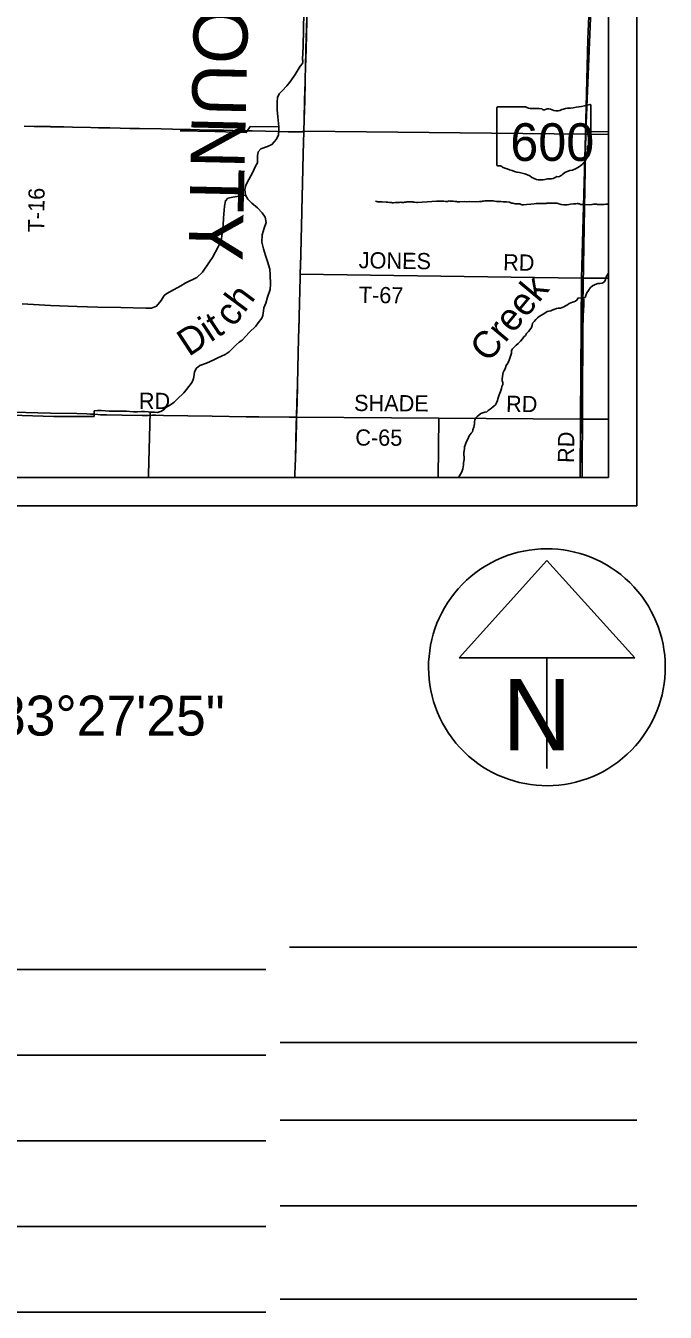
# Model space of a CAD drawing. Extents: x -8.3 to 42.1, y 0 to 22.
# Drawn here: x 6.858 to 9.099, y 11.177 to 15.682 of the extents above; entities that cross this region are included whole.
import ezdxf

# ---------------------------------------------------------------- set-up
doc = ezdxf.new("R2010")
doc.units = 0
for name, color, linetype in [('Default', 7, 'Continuous'), ('GM_X_County_Road', 7, 'Continuous'), ('GM_X_County_Road_Text', 7, 'Continuous'), ('GM_X_County_Text', 7, 'Continuous'), ('GM_X_Minor_River', 7, 'Continuous'), ('GM_X_Minor_River_Text', 7, 'Continuous'), ('GM_X_State_Location', 7, 'Continuous'), ('GM_X_State_Route', 7, 'Continuous'), ('GM_X_State_Shield', 7, 'Continuous'), ('GM_X_Township_Road', 7, 'Continuous'), ('GM_X_Township_Road_Text', 7, 'Continuous'), ('GM_X_US_Route', 7, 'Continuous'), ('SH_Cut_Line', 7, 'Continuous'), ('SH_Data', 7, 'Continuous'), ('SH_Text', 7, 'Continuous')]:
    doc.layers.add(name, color=color, linetype=linetype)

msp = doc.modelspace()

# ---------------------------------------------------------------- linework, layer by layer
at = {"layer": 'Default'}
for points in [[(8.9, 15.3104), (8.9, 16.3044), (8.8613, 16.3047), (8.821, 15.3114)], [(8.9, 14.3033), (8.9, 15.3104), (8.821, 15.3114), (8.8035, 14.3039)], [(8.8012, 14.1), (8.9, 14.1), (8.9, 14.3033), (8.8035, 14.3039)]]:
    msp.add_lwpolyline(points, close=True, dxfattribs=at)
at = {"layer": 'GM_X_County_Road'}
msp.add_lwpolyline([(7.8073, 14.3105), (8.306, 14.307), (8.8027, 14.3043), (8.9, 14.3037)], dxfattribs=at)
at = {"layer": 'GM_X_Minor_River'}
for p, q in [((8.8101, 14.6407), (8.8101, 14.6411)), ((8.8103, 14.6206), (8.8085, 14.1))]:
    msp.add_line(p, q, dxfattribs=at)
for points in [[(7.833, 15.7279), (7.8304, 15.6084), (7.8285, 15.5633), (7.8292, 15.5602), (7.8291, 15.5549), (7.8278, 15.5496), (7.82, 15.5396), (7.8019, 15.5104), (7.7877, 15.4888), (7.7729, 15.4713), (7.7565, 15.4542), (7.7468, 15.4427), (7.7408, 15.4303), (7.7389, 15.4137), (7.7397, 15.3871), (7.7414, 15.3627), (7.7451, 15.3274), (7.7448, 15.3148), (7.7436, 15.2993), (7.7372, 15.2843), (7.7208, 15.2657), (7.7055, 15.2592), (7.6826, 15.2511), (7.6728, 15.2395), (7.6699, 15.2267), (7.67, 15.202), (7.6629, 15.1901), (7.654, 15.1683), (7.6401, 15.1436), (7.6294, 15.1237), (7.626, 15.1078), (7.6278, 15.0884), (7.6365, 15.0746), (7.651, 15.0602), (7.6699, 15.0445), (7.6872, 15.0263), (7.6975, 15.0116), (7.7008, 14.9925), (7.6942, 14.9726), (7.6872, 14.9496), (7.6858, 14.9238), (7.6909, 14.8998), (7.6983, 14.8776), (7.7054, 14.8566), (7.7134, 14.8287), (7.7152, 14.81), (7.7159, 14.777), (7.7143, 14.7581), (7.7049, 14.7317), (7.6991, 14.7102), (7.693, 14.6941), (7.6916, 14.6838), (7.6889, 14.6672), (7.686, 14.6578), (7.6731, 14.6413)], [(7.7451, 15.3274), (7.6448, 15.329), (7.631, 15.3073), (7.5224, 15.3111), (7.399, 15.3134)], [(7.6278, 15.0884), (7.5841, 15.0815), (7.5666, 15.0774), (7.5584, 15.0689), (7.5549, 15.0492), (7.5508, 15.0083), (7.5498, 14.9829), (7.5465, 14.9538), (7.5432, 14.9288), (7.5328, 14.9071), (7.5129, 14.8696), (7.5027, 14.8547), (7.478, 14.8181), (7.4578, 14.8003), (7.4168, 14.7805), (7.4018, 14.7709), (7.3523, 14.7441), (7.3438, 14.7367), (7.3331, 14.7195), (7.3167, 14.6994), (7.2995, 14.6926), (7.2791, 14.6927), (7.1916, 14.6952), (7.1106, 14.696), (7.038, 14.6989), (6.9453, 14.7016), (6.8458, 14.7082)], [(8.3763, 15.0655), (8.3736, 15.0655), (8.371, 15.0652), (8.3679, 15.0656), (8.3615, 15.0661), (8.3555, 15.0669), (8.3452, 15.0674), (8.3415, 15.0679), (8.3361, 15.0664), (8.3335, 15.0661), (8.3293, 15.0665), (8.3229, 15.067), (8.3149, 15.0667), (8.3097, 15.0675), (8.3066, 15.0675), (8.2975, 15.0673), (8.2809, 15.0664), (8.2312, 15.0628), (8.2274, 15.0625), (8.2202, 15.0634), (8.2172, 15.0634), (8.2142, 15.0646), (8.2097, 15.065), (8.2063, 15.0654), (8.1975, 15.0655), (8.1938, 15.0652), (8.1907, 15.0641), (8.1854, 15.0634), (8.182, 15.0631), (8.179, 15.0628), (8.1759, 15.0628), (8.1729, 15.0632), (8.168, 15.0629), (8.1589, 15.063), (8.1551, 15.0627), (8.1524, 15.0627), (8.1475, 15.062), (8.1437, 15.0617), (8.1403, 15.0621), (8.1354, 15.0629), (8.1328, 15.063), (8.1275, 15.0638), (8.1207, 15.0639), (8.1067, 15.0644), (8.1032, 15.0645), (8.0976, 15.0649), (8.0942, 15.065), (8.0915, 15.0654), (8.0881, 15.0662), (8.0844, 15.0674)], [(8.9, 15.0564), (8.8911, 15.0566), (8.8846, 15.0559), (8.8774, 15.056), (8.8748, 15.0556), (8.8695, 15.0553), (8.8668, 15.0553), (8.8619, 15.0558), (8.8585, 15.0562), (8.8544, 15.0566), (8.8513, 15.0567), (8.8479, 15.0564), (8.8422, 15.0553), (8.8346, 15.0546), (8.8191, 15.0552), (8.8119, 15.0553), (8.8055, 15.0558), (8.8025, 15.0558), (8.7991, 15.0574), (8.7964, 15.0582), (8.793, 15.0586), (8.7904, 15.0586), (8.7862, 15.0583), (8.7779, 15.058), (8.7673, 15.0566), (8.7555, 15.0549), (8.7438, 15.0547), (8.7343, 15.0559), (8.7264, 15.0579), (8.7204, 15.0599), (8.717, 15.0603), (8.7143, 15.0607), (8.7109, 15.0604), (8.7052, 15.0597), (8.6984, 15.0598), (8.6874, 15.0603), (8.6844, 15.0604), (8.6817, 15.0596), (8.6764, 15.059), (8.6681, 15.0587), (8.6598, 15.0588), (8.6514, 15.0593), (8.6465, 15.059), (8.6397, 15.0579), (8.6279, 15.0569), (8.6128, 15.0556), (8.6025, 15.055), (8.5984, 15.055), (8.5882, 15.0574), (8.5825, 15.0575), (8.578, 15.058), (8.5738, 15.0584), (8.5651, 15.06), (8.5614, 15.0608), (8.558, 15.062), (8.5531, 15.0636), (8.5425, 15.0649), (8.5315, 15.0654), (8.5236, 15.0659), (8.5152, 15.066), (8.5073, 15.0665), (8.496, 15.0681), (8.4888, 15.0682), (8.4812, 15.0687), (8.4759, 15.0688), (8.4702, 15.0685), (8.4676, 15.0685), (8.463, 15.0674), (8.4592, 15.0667), (8.4565, 15.0664), (8.4512, 15.066), (8.4486, 15.0657), (8.4331, 15.0655), (8.4122, 15.0658), (8.4039, 15.0651), (8.3944, 15.0656), (8.3789, 15.0651), (8.3763, 15.0655)], [(8.9, 14.8154), (8.898, 14.8111), (8.8927, 14.802), (8.8897, 14.7932), (8.8859, 14.7852), (8.8784, 14.7799), (8.8708, 14.7791), (8.8628, 14.7787), (8.8537, 14.7756), (8.8446, 14.771), (8.8359, 14.7633), (8.8299, 14.7549), (8.8239, 14.7462), (8.8209, 14.7367), (8.8184, 14.7305)], [(8.8184, 14.7305), (8.7924, 14.7275), (8.7905, 14.7218), (8.7848, 14.7169), (8.7794, 14.7153), (8.7737, 14.7134), (8.768, 14.7112), (8.762, 14.7085), (8.7563, 14.7039), (8.7502, 14.7009), (8.7437, 14.6967), (8.738, 14.6944), (8.7316, 14.6929), (8.7243, 14.6925), (8.7179, 14.6914), (8.7118, 14.6895), (8.7057, 14.6872), (8.6977, 14.6838), (8.692, 14.6823), (8.686, 14.6804), (8.6806, 14.6773), (8.6719, 14.672), (8.6635, 14.6675), (8.6578, 14.6637), (8.6514, 14.6591), (8.646, 14.6526), (8.6396, 14.6462), (8.6343, 14.6405), (8.6331, 14.6314), (8.6308, 14.6249), (8.6244, 14.6169), (8.6202, 14.6112), (8.6133, 14.6036), (8.6092, 14.5971), (8.6035, 14.5922), (8.5989, 14.5854), (8.5917, 14.577), (8.5841, 14.5686), (8.5772, 14.5626), (8.5685, 14.555), (8.5628, 14.5496), (8.5609, 14.5436), (8.5605, 14.5352), (8.5578, 14.5284), (8.5552, 14.5208), (8.5521, 14.5109), (8.5472, 14.5002), (8.5422, 14.4915), (8.5384, 14.4801), (8.5343, 14.4744), (8.5316, 14.4679), (8.5297, 14.4615), (8.5289, 14.4539), (8.5282, 14.4447), (8.5282, 14.4383), (8.5301, 14.4322), (8.5297, 14.425), (8.527, 14.4185), (8.5255, 14.4109), (8.5221, 14.4003), (8.5198, 14.3946), (8.5167, 14.3892), (8.5152, 14.382), (8.5129, 14.3752), (8.5118, 14.3695), (8.508, 14.3611), (8.5038, 14.3543), (8.4985, 14.3489), (8.492, 14.3436), (8.4856, 14.3391), (8.4791, 14.3341), (8.4738, 14.3299), (8.4673, 14.3284), (8.4601, 14.3265), (8.4533, 14.3235), (8.446, 14.3174), (8.4403, 14.3136), (8.4358, 14.3083), (8.4316, 14.3011), (8.4304, 14.2946), (8.4304, 14.2878), (8.4289, 14.2756), (8.4251, 14.2661), (8.424, 14.26), (8.419, 14.2547), (8.4122, 14.2456), (8.4072, 14.2334), (8.4012, 14.2235), (8.3981, 14.2125), (8.3958, 14.2072), (8.3958, 14.2015), (8.3943, 14.1927), (8.3932, 14.187), (8.3935, 14.1817), (8.3943, 14.1688), (8.3947, 14.1631), (8.3935, 14.1574), (8.3924, 14.1513), (8.392, 14.1437), (8.3897, 14.1304), (8.3878, 14.1236)], [(8.8103, 14.6201), (8.8113, 14.6619), (8.8118, 14.6653), (8.8119, 14.6755), (8.8123, 14.6789), (8.8124, 14.6854), (8.8129, 14.6884), (8.8129, 14.6918), (8.8134, 14.6964), (8.8138, 14.6998), (8.8138, 14.7032), (8.8143, 14.7066), (8.8144, 14.7142), (8.814, 14.7168), (8.8134, 14.7214), (8.8112, 14.7297)], [(7.6731, 14.6413), (7.6651, 14.6294), (7.6417, 14.6073), (7.6292, 14.5944), (7.617, 14.5807), (7.6065, 14.573), (7.596, 14.5642), (7.5839, 14.5524), (7.5714, 14.5402), (7.557, 14.5307), (7.5443, 14.5247), (7.5312, 14.5182), (7.5173, 14.5114), (7.505, 14.5057), (7.4919, 14.5), (7.4689, 14.4915), (7.4561, 14.4828), (7.45, 14.4697), (7.4486, 14.4591), (7.4463, 14.4462), (7.441, 14.4338), (7.4299, 14.4182), (7.422, 14.4074), (7.4118, 14.3959), (7.3884, 14.3738), (7.3786, 14.3638), (7.3654, 14.354), (7.3553, 14.3486), (7.344, 14.3386), (7.3316, 14.331), (7.319, 14.3276), (7.3095, 14.3279), (7.2974, 14.3286), (7.2871, 14.3293), (7.2743, 14.3308), (7.264, 14.3307), (7.2495, 14.3296), (7.2359, 14.3296), (7.2233, 14.3304), (7.2116, 14.3315), (7.1979, 14.3323), (7.1842, 14.3319), (7.1728, 14.3319), (7.1633, 14.3318), (7.1508, 14.3317), (7.1375, 14.3329), (7.1243, 14.3337), (7.1102, 14.3348), (7.0976, 14.3332)], [(8.8128, 14.6311), (8.8127, 14.6311)], [(7.0976, 14.3332), (7.0975, 14.3135), (6.9572, 14.3135), (6.808, 14.3174), (6.8025, 14.1535), (6.8011, 14.1)], [(7.2947, 14.3288), (7.2888, 14.1104), (7.2885, 14.1)], [(8.3878, 14.1236), (8.3855, 14.1175), (8.3817, 14.111), (8.3779, 14.1057), (8.3749, 14.1)]]:
    msp.add_lwpolyline(points, dxfattribs=at)
at = {"layer": 'GM_X_State_Route'}
msp.add_lwpolyline([(7.8327, 15.3119), (8.8198, 15.3016), (8.9, 15.3008)], dxfattribs=at)
at = {"layer": 'GM_X_State_Shield'}
for p, q in [((8.5093, 15.3943), (8.5093, 15.1942)), ((8.609, 15.3978), (8.5125, 15.3978)), ((8.8389, 15.2981), (8.8389, 15.4027)), ((8.8388, 15.2981), (8.8389, 15.2981))]:
    msp.add_line(p, q, dxfattribs=at)
for centre, major_axis, start_param, end_param in [((8.5131, 15.3948), (0.00382, 0), 1.712693, 3.28349), ((8.632, 15.421), (0.037, 0), 4.042523, 4.731795), ((8.6443, 15.2854), (0.133, 0), 1.404758, 1.657858), ((8.6745, 15.3958), (0.0107, 0), 3.836095, 5.185415), ((8.6902, 15.3727), (0.0222, 0), 0.950623, 2.079405), ((8.7188, 15.4044), (0.0267, 0), 4.081561, 5.145723), ((8.766, 15.3367), (0.0703, 0), 1.699011, 2.107814), ((8.7215, 15.6706), (0.3495, 0), 4.814394, 5.042369), ((8.8352, 15.4032), (0.00367, 0), 6.141152, 7.989035), ((8.838, 15.2904), (0.00568, 0), 1.883978, 3.671073), ((8.8019, 15.2771), (0.0341, 0), 5.934695, 6.695948), ((8.8349, 15.2976), (0.00393, 0), 5.05454, 6.418171), ((8.741, 15.2409), (0.0874, 0), 5.101752, 6.440018), ((8.852, 15.2542), (0.0248, 0), 2.387724, 3.262537), ((8.5131, 15.1938), (0.00385, 0), 3.00124, 4.508301), ((8.5137, 15.2143), (0.0294, 0), 4.665946, 4.897461), ((8.5197, 15.1827), (0.0106, 0), 0.519207, 1.627899), ((8.6535, 15.3625), (0.2524, 0), 4.195997, 4.488961), ((8.5783, 15.1043), (0.079, 0), 0.823519, 1.323587), ((8.6637, 15.1817), (0.0501, 0), 4.026481, 4.996735), ((8.6926, 15.1125), (0.0412, 0), 1.495662, 1.94098), ((8.6963, 15.1667), (0.0267, 0), 4.691044, 5.507374), ((8.7204, 15.1473), (0.00752, 0), 1.147584, 2.315152), ((8.7172, 15.1748), (0.0282, 0), 4.937069, 5.64225), ((8.7779, 15.138), (0.0479, 0), 1.647645, 2.488434)]:
    msp.add_ellipse(centre, major_axis=major_axis, ratio=0.8, start_param=start_param, end_param=end_param, dxfattribs=at)
at = {"layer": 'GM_X_Township_Road'}
for p, q in [((7.8204, 14.812), (8.8057, 14.7977)), ((8.8057, 14.7977), (8.9, 14.7971)), ((8.3033, 14.1), (8.306, 14.307)), ((8.8006, 14.1), (8.8027, 14.3043))]:
    msp.add_line(p, q, dxfattribs=at)
for points in [[(7.844, 15.7482), (7.8403, 15.6006), (7.8387, 15.5353), (7.8376, 15.4981), (7.8374, 15.4841), (7.8356, 15.4204), (7.8337, 15.3535), (7.8325, 15.3124), (7.8306, 15.2323), (7.8281, 15.1298), (7.8258, 15.035), (7.8243, 14.9759), (7.8232, 14.9386), (7.8218, 14.8765), (7.8202, 14.8125), (7.8201, 14.8066), (7.8185, 14.7491), (7.8175, 14.7164), (7.8163, 14.6574), (7.8143, 14.5859), (7.8115, 14.4834), (7.8101, 14.4243), (7.8086, 14.3606), (7.8071, 14.311), (7.8064, 14.2876), (7.8034, 14.1648), (7.8025, 14.1415), (7.8014, 14.1104), (7.8015, 14.1089), (7.8013, 14.1027), (7.8013, 14.1), (8.9, 14.1), (8.9, 16.8007)], [(8.8198, 15.3016), (8.828, 15.6349), (8.835, 15.7975), (8.8508, 16.125), (8.8664, 16.6469), (8.8745, 16.8004)], [(2.1, 14.1), (7.8013, 14.1), (7.8013, 14.1027), (7.8015, 14.1089), (7.8014, 14.1104), (7.8025, 14.1415), (7.8034, 14.1648), (7.8064, 14.2876), (7.8071, 14.311), (7.8086, 14.3606), (7.8101, 14.4243), (7.8115, 14.4834), (7.8143, 14.5859), (7.8163, 14.6574), (7.8175, 14.7164), (7.8185, 14.7491), (7.8201, 14.8066), (7.8202, 14.8125), (7.8218, 14.8765), (7.8232, 14.9386), (7.8243, 14.9759), (7.8258, 15.035), (7.8281, 15.1298), (7.8306, 15.2323), (7.8325, 15.3124), (7.8337, 15.3535), (7.8356, 15.4204), (7.8374, 15.4841), (7.8376, 15.4981), (7.8387, 15.5353), (7.8403, 15.6006), (7.844, 15.7482)], [(6.8533, 15.3297), (6.8874, 15.3292), (6.9201, 15.3286), (6.9434, 15.3282), (6.9465, 15.3281), (6.9915, 15.3272), (7.0226, 15.3266), (7.0863, 15.3253), (7.1127, 15.3246), (7.1329, 15.324), (7.1531, 15.3235), (7.1888, 15.3226), (7.2229, 15.322), (7.2571, 15.3215), (7.3333, 15.3201), (7.3721, 15.3192), (7.4001, 15.3188), (7.4358, 15.3179), (7.4668, 15.3172), (7.5135, 15.3163), (7.5383, 15.3159), (7.5507, 15.3157), (7.5834, 15.3149), (7.6222, 15.314), (7.6517, 15.3132), (7.6983, 15.3121), (7.7403, 15.3112), (7.7775, 15.3106), (7.8055, 15.3103), (7.821, 15.31), (7.8242, 15.3101), (7.8273, 15.3104), (7.8297, 15.311), (7.8327, 15.3119)], [(8.8027, 14.3043), (8.8057, 14.7977), (8.8198, 15.3016)], [(6.8271, 14.3279), (6.8582, 14.3272), (6.9001, 14.3262), (6.9452, 14.3253), (7.0368, 14.3234), (7.0726, 14.3226), (7.0849, 14.322), (7.0958, 14.3211), (7.1113, 14.3198), (7.1206, 14.3193), (7.1408, 14.3189), (7.1967, 14.318), (7.2667, 14.3169), (7.2869, 14.3169), (7.3024, 14.3174), (7.3133, 14.3174), (7.3412, 14.317), (7.4267, 14.3157), (7.5121, 14.3144), (7.6302, 14.3125), (7.6753, 14.3117), (7.7809, 14.3104), (7.7996, 14.3104), (7.8073, 14.3105)]]:
    msp.add_lwpolyline(points, dxfattribs=at)
at = {"layer": 'GM_X_US_Route'}
msp.add_lwpolyline([(7.8015, 14.1), (7.8015, 14.1021), (7.8017, 14.1083), (7.8016, 14.1099), (7.8028, 14.1409), (7.8036, 14.1642), (7.8066, 14.287), (7.8073, 14.3105), (7.8089, 14.36), (7.8104, 14.4237), (7.8117, 14.4828), (7.8145, 14.5854), (7.8165, 14.6568), (7.8178, 14.7159), (7.8187, 14.7485), (7.8203, 14.806), (7.8204, 14.812), (7.822, 14.8759), (7.8234, 14.9381), (7.8245, 14.9754), (7.826, 15.0344), (7.8284, 15.1292), (7.8308, 15.2318), (7.8327, 15.3119), (7.834, 15.353), (7.8358, 15.4198), (7.8376, 15.4835), (7.8378, 15.4975), (7.8389, 15.5348), (7.8405, 15.6001), (7.8442, 15.7477)], dxfattribs=at)
at = {"layer": 'SH_Cut_Line'}
for points in [[(7.844, 15.7482), (7.8403, 15.6006), (7.8387, 15.5353), (7.8376, 15.4981), (7.8374, 15.4841), (7.8356, 15.4204), (7.8337, 15.3535), (7.8325, 15.3124), (7.8306, 15.2323), (7.8281, 15.1298), (7.8258, 15.035), (7.8243, 14.9759), (7.8232, 14.9386), (7.8218, 14.8765), (7.8202, 14.8125), (7.8201, 14.8066), (7.8185, 14.7491), (7.8175, 14.7164), (7.8163, 14.6574), (7.8143, 14.5859), (7.8115, 14.4834), (7.8101, 14.4243), (7.8086, 14.3606), (7.8071, 14.311), (7.8064, 14.2876), (7.8034, 14.1648), (7.8025, 14.1415), (7.8014, 14.1104), (7.8015, 14.1089), (7.8013, 14.1027), (7.8013, 14.1), (8.9, 14.1), (8.9, 20.9)], [(2.1, 14.1), (7.8013, 14.1), (7.8013, 14.1027), (7.8015, 14.1089), (7.8014, 14.1104), (7.8025, 14.1415), (7.8034, 14.1648), (7.8064, 14.2876), (7.8071, 14.311), (7.8086, 14.3606), (7.8101, 14.4243), (7.8115, 14.4834), (7.8143, 14.5859), (7.8163, 14.6574), (7.8175, 14.7164), (7.8185, 14.7491), (7.8201, 14.8066), (7.8202, 14.8125), (7.8218, 14.8765), (7.8232, 14.9386), (7.8243, 14.9759), (7.8258, 15.035), (7.8281, 15.1298), (7.8306, 15.2323), (7.8325, 15.3124), (7.8337, 15.3535), (7.8356, 15.4204), (7.8374, 15.4841), (7.8376, 15.4981), (7.8387, 15.5353), (7.8403, 15.6006), (7.844, 15.7482)]]:
    msp.add_lwpolyline(points, dxfattribs=at)
at = {"layer": 'SH_Data'}
for p, q in [((9, 21), (9, 14)), ((8.9, 20.9), (8.9, 14.1)), ((2.1, 14.1), (8.9, 14.1)), ((2, 14), (9, 14)), ((8.6845, 13.8091), (8.3769, 13.4678)), ((8.9921, 13.4678), (8.6845, 13.8091)), ((8.3769, 13.4678), (8.9921, 13.4678)), ((8.6845, 13.4678), (8.6845, 13.0811)), ((8.6845, 13.4353), (8.6845, 13.4353)), ((8.6845, 13.4353), (8.6845, 13.4353)), ((7.7827, 12.4553), (9, 12.4553)), ((7.7, 12.3767), (4.4937, 12.3767)), ((9, 12.1207), (7.75, 12.1207)), ((7.7, 12.0767), (3.9895, 12.0767)), ((9, 11.8491), (7.75, 11.8491)), ((7.7, 11.7767), (3.6192, 11.7767)), ((9, 11.5491), (7.75, 11.5491)), ((7.7, 11.4767), (3.3288, 11.4767)), ((9, 11.2223), (7.75, 11.2223)), ((7.7, 11.1767), (4.7452, 11.1767))]:
    msp.add_line(p, q, dxfattribs=at)
msp.add_arc((8.6845, 13.4353), 0.4148, 129.7798, 129.7633, dxfattribs=at)

# ---------------------------------------------------------------- texts
at = {"layer": 'GM_X_County_Road_Text'}
for s, rotation, p in [('SHADE', 359.588, (8.0087, 14.3326)), ('RD', 359.5064, (8.5412, 14.3293)), ('C-65', 359.6571, (8.0129, 14.2115))]:
    msp.add_text(s, height=0.05682, rotation=rotation, dxfattribs=at).set_placement(p)
at = {"layer": 'GM_X_County_Text'}
msp.add_text('WOOD COUNTY', height=0.189394, rotation=268.7124, dxfattribs=at).set_placement((7.4724, 16.8159))
at = {"layer": 'GM_X_Minor_River_Text'}
for s, height, rotation, p in [('Creek', 0.09476, 50.113, (8.4796, 14.4987)), ('ch', 0.09476, 53.3151, (7.5867, 14.6228)), ('Dit', 0.09475, 33.3141, (7.4294, 14.5212))]:
    msp.add_text(s, height=height, rotation=rotation, dxfattribs=at).set_placement(p)
at = {"layer": 'GM_X_State_Location'}
for s in ['s', 'r']:
    msp.add_text(s, height=0.000189, dxfattribs=at).set_placement((8.6704, 15.281))
msp.add_text('600', height=0.000189, rotation=0, dxfattribs=at).set_placement((8.6035, 15.2672))
at = {"layer": 'GM_X_State_Shield'}
msp.add_text('600', height=0.13184, dxfattribs=at).set_placement((8.5562, 15.2083))
at = {"layer": 'GM_X_Township_Road_Text'}
for s, rotation, p in [('T-16', 89.2959, (6.9228, 14.9576)), ('JONES', 359.0838, (8.0247, 14.8326)), ('RD', 359.0128, (8.5306, 14.8251)), ('T-67', 358.9397, (8.025, 14.7116)), ('RD', 359.5129, (7.2544, 14.34)), ('RD', 89.5063, (8.7795, 14.1504))]:
    msp.add_text(s, height=0.05682, rotation=rotation, dxfattribs=at).set_placement(p)
at = {"layer": 'SH_Data'}
msp.add_text('N', height=0.25, dxfattribs=at).set_placement((8.5292, 13.144))
at = {"layer": 'SH_Text'}
msp.add_text('LATITUDE:  N41°24\'33"     LONGITUDE:  W83°27\'25"', height=0.14, dxfattribs=at).set_placement((3.071, 13.1959))

doc.saveas('drawing.dxf')
